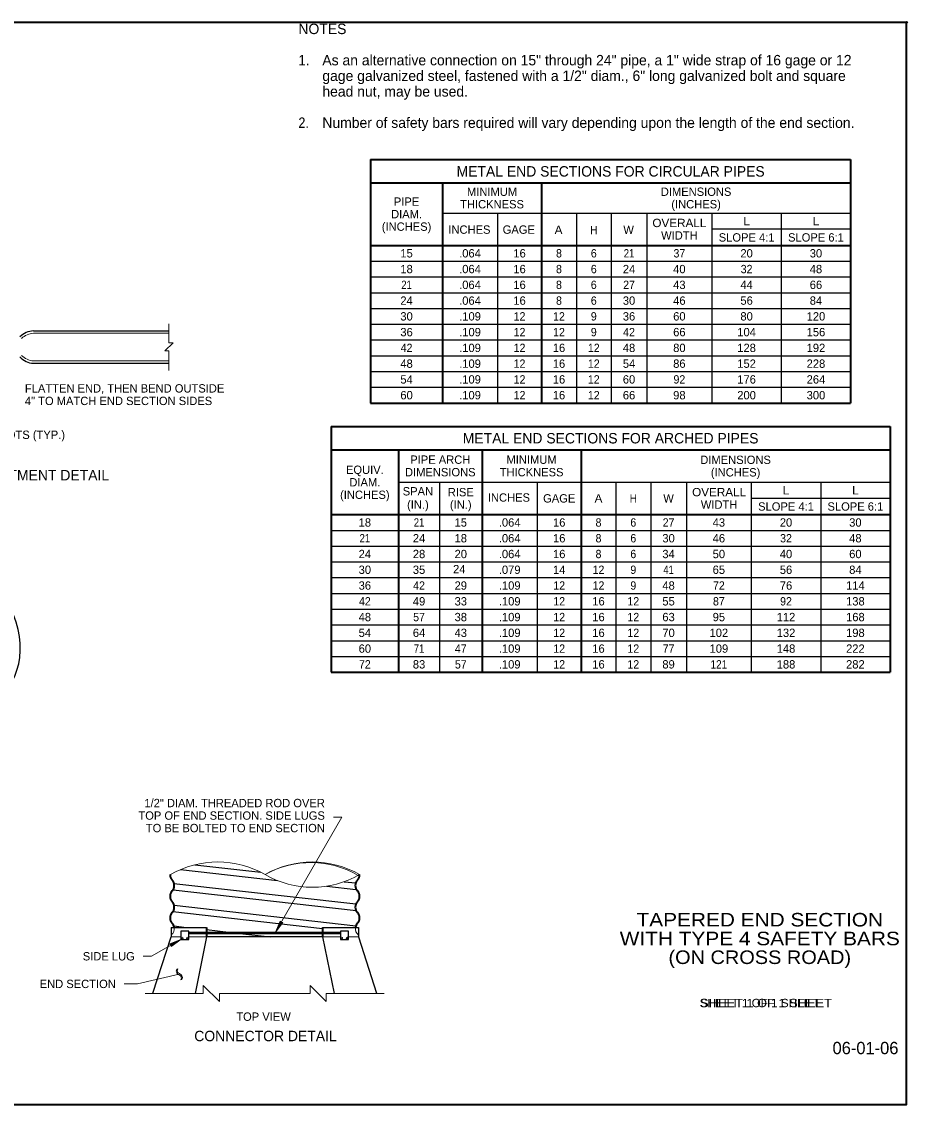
# Model space of a CAD drawing. Extents: x 99860 to 103153, y 99998 to 102077.
# Drawn here: x 101453 to 103153, y 100000 to 102077 of the extents above; entities that cross this region are included whole.
import ezdxf
from ezdxf.enums import TextEntityAlignment as Align

# ---------------------------------------------------------------- set-up
doc = ezdxf.new("R2010")
doc.units = 0
doc.header["$LTSCALE"] = 6.4
doc.header["$PDMODE"] = 32
doc.header["$PDSIZE"] = 3.2
for name, color, linetype, lineweight in [('1', 7, 'Continuous', 35), ('15', 7, 'Continuous', 13), ('18', 7, 'Continuous', 25), ('19', 7, 'Continuous', 25), ('20', 7, 'Continuous', 13), ('6', 7, 'Continuous', 25)]:
    doc.layers.add(name, color=color, linetype=linetype, lineweight=lineweight)
for name, color, linetype in [('11', 7, 'Continuous'), ('60', 7, 'Continuous'), ('62', 7, 'Continuous'), ('63', 7, 'Continuous')]:
    doc.layers.add(name, color=color, linetype=linetype)

msp = doc.modelspace()

# ---------------------------------------------------------------- hatches: boundary and pattern name
at = {"layer": '15'}
for points in [[(101939.857, 100330.015), (101948.687, 100351.278), (101950.744, 100348.871), (101953.857, 100348.293)], [(101758.02, 100316.136), (101736.757, 100307.306), (101739.164, 100305.249), (101739.742, 100302.136)]]:
    msp.add_hatch(color=256, dxfattribs=at).paths.add_polyline_path(points)

# ---------------------------------------------------------------- linework, layer by layer
at = {"layer": '1'}
msp.add_lwpolyline([(99862, 99999.5), (103151, 99999.5), (103151, 102075.5), (99862, 102075.5)], close=True, dxfattribs=at)
at = {"layer": '15'}
for p, q in [((101939.857, 100330.015), (102067.375, 100550.882)), ((102051.375, 100550.882), (102067.375, 100550.882)), ((101758.02, 100316.135), (101701.728, 100283.635)), ((101685.728, 100283.635), (101701.728, 100283.635))]:
    msp.add_line(p, q, dxfattribs=at)
for points in [[(101735.376, 101497.024), (101735.376, 101460.814), (101743.119, 101460.814), (101727.633, 101445.328), (101735.376, 101445.328), (101735.376, 101407.991)], [(101919.135, 100212.225), (101832.027, 100212.225), (101832.027, 100196.739), (101801.055, 100227.711), (101801.055, 100212.225), (101689.467, 100212.225)], [(102148.494, 100212.225), (102037.215, 100212.225), (102037.215, 100196.739), (102006.243, 100227.711), (102006.243, 100212.225), (101919.135, 100212.225)]]:
    msp.add_lwpolyline(points, dxfattribs=at)
for points in [[(101939.857, 100330.015), (101948.687, 100351.278), (101950.744, 100348.871), (101953.857, 100348.293)], [(101758.02, 100316.136), (101736.757, 100307.306), (101739.164, 100305.249), (101739.742, 100302.136)]]:
    msp.add_lwpolyline(points, close=True, dxfattribs=at)
at = {"layer": '18'}
for p, q in [((101475.087, 101483.84), (101734.737, 101483.84)), ((101475.147, 101421.75), (101734.737, 101421.75)), ((101739.76, 100339.165), (101807.66, 100339.165)), ((101739.76, 100339.165), (101739.76, 100320.995)), ((101773.44, 100330.015), (102064.31, 100330.015)), ((101773.44, 100327.585), (102064.31, 100327.585)), ((101704.23, 100212.705), (101739.772, 100320.991)), ((101807.66, 100320.995), (101785.77, 100212.495)), ((102030.31, 100320.995), (102052.2, 100212.495))]:
    msp.add_line(p, q, dxfattribs=at)
at = {"layer": '18', "lineweight": 13}
for p, q in [((101475.287, 101479.37), (101734.737, 101479.37)), ((101475.147, 101426.21), (101734.737, 101426.21))]:
    msp.add_line(p, q, dxfattribs=at)
at = {"layer": '18', "lineweight": 35}
for p, q in [((101807.66, 100339.165), (101807.66, 100330.015)), ((101807.66, 100327.585), (101807.66, 100320.995)), ((102030.31, 100339.165), (102030.31, 100330.015)), ((102030.31, 100327.585), (102030.31, 100320.995))]:
    msp.add_line(p, q, dxfattribs=at)
at = {"layer": '18'}
for points in [[(101773.44, 100331.635), (101758.02, 100331.635), (101758.02, 100316.135), (101773.44, 100316.135)], [(102079.81, 100331.635), (102064.31, 100331.635), (102064.31, 100316.135), (102079.81, 100316.135)]]:
    msp.add_lwpolyline(points, close=True, dxfattribs=at)
msp.add_lwpolyline([(102030.31, 100339.165), (102099.42, 100339.165), (102099.42, 100320.995), (102133.67, 100212.915)], dxfattribs=at)
for centre, radius, start, end in [((101479.006, 101439.497), 44.512, 94.97013, 131.98006), ((101476.264, 101458.194), 36.47, 222.16871, 268.2497)]:
    msp.add_arc(centre, radius, start, end, dxfattribs=at)
at = {"layer": '18', "lineweight": 13}
for centre, radius, start, end in [((101479.006, 101439.497), 40.045, 94.97013, 131.98006), ((101476.264, 101458.194), 32.003, 222.16871, 268.2497), ((101760.662, 100318.575), 1.613, 0, 180), ((101760.662, 100318.575), 1.613, 180, 0), ((101770.738, 100318.575), 1.613, 0, 180), ((101770.738, 100318.575), 1.613, 180, 0), ((102066.998, 100318.575), 1.613, 0, 180), ((102066.998, 100318.575), 1.613, 180, 0), ((102077.074, 100318.575), 1.613, 0, 180), ((102077.074, 100318.575), 1.613, 180, 0)]:
    msp.add_arc(centre, radius, start, end, dxfattribs=at)
at = {"layer": '19', "lineweight": 35}
for p, q in [((102122.379, 101812.42), (103043.649, 101812.42)), ((102122.379, 101812.42), (102122.379, 101345.22)), ((103043.649, 101812.42), (103043.649, 101345.22)), ((102122.379, 101767.79), (103043.649, 101767.79)), ((102260.359, 101767.79), (102260.359, 101345.22)), ((102450.519, 101767.79), (102450.519, 101345.22)), ((102122.379, 101647.72), (103043.649, 101647.72)), ((102122.379, 101345.22), (103043.649, 101345.22)), ((102046.594, 101300.22), (102046.594, 100828.7)), ((102046.594, 101300.22), (103119.434, 101300.22)), ((103119.434, 101300.22), (103119.434, 100828.7)), ((102046.594, 101255.22), (103119.434, 101255.22)), ((102175.994, 101255.22), (102175.994, 100828.7)), ((102336.224, 101255.22), (102336.224, 100828.7)), ((102526.384, 101255.22), (102526.384, 100828.7)), ((102046.594, 101131.2), (103119.434, 101131.2)), ((102046.594, 100828.7), (103119.434, 100828.7))]:
    msp.add_line(p, q, dxfattribs=at)
at = {"layer": '19'}
for p, q in [((102260.359, 101709.74), (103043.649, 101709.74)), ((102365.949, 101709.74), (102365.949, 101345.22)), ((102517.289, 101709.74), (102517.289, 101345.22)), ((102584.129, 101709.74), (102584.129, 101345.22)), ((102652.639, 101709.74), (102652.639, 101345.22)), ((102777.379, 101709.74), (102777.379, 101345.22)), ((102910.689, 101709.74), (102910.689, 101345.22)), ((103043.849, 101678.63), (102777.529, 101678.63)), ((102122.379, 101617.47), (103043.649, 101617.47)), ((102122.379, 101587.22), (103043.649, 101587.22)), ((102122.379, 101556.97), (103043.649, 101556.97)), ((102122.379, 101526.72), (103043.649, 101526.72)), ((102122.379, 101496.47), (103043.649, 101496.47)), ((102122.379, 101466.22), (103043.649, 101466.22)), ((102122.379, 101435.97), (103043.649, 101435.97)), ((102122.379, 101405.72), (103043.649, 101405.72)), ((102122.379, 101375.47), (103043.649, 101375.47)), ((102175.994, 101193.42), (103119.434, 101193.42)), ((102254.634, 101193.42), (102254.634, 100828.7)), ((102442.364, 101193.42), (102442.364, 100828.7)), ((102593.154, 101193.42), (102593.154, 100828.7)), ((102659.994, 101193.42), (102659.994, 100828.7)), ((102728.504, 101193.42), (102728.504, 100828.7)), ((102853.114, 101193.42), (102853.114, 100828.7)), ((102986.274, 101193.42), (102986.274, 100828.7)), ((103119.434, 101162.31), (102853.114, 101162.31)), ((102046.594, 101100.95), (103119.434, 101100.95)), ((102046.594, 101070.7), (103119.434, 101070.7)), ((102046.594, 101040.45), (103119.434, 101040.45)), ((102046.594, 101010.2), (103119.434, 101010.2)), ((102046.594, 100979.95), (103119.434, 100979.95)), ((102046.594, 100949.7), (103119.434, 100949.7)), ((102046.594, 100919.45), (103119.434, 100919.45)), ((102046.594, 100889.2), (103119.434, 100889.2)), ((102046.594, 100858.95), (103119.434, 100858.95))]:
    msp.add_line(p, q, dxfattribs=at)
at = {"layer": '20'}
for p, q in [((101755.18, 100249.005), (101674.84, 100230.605)), ((101752.248, 100259.85), (101750.418, 100258.793)), ((101649.34, 100230.605), (101674.84, 100230.605)), ((101758.15, 100238.156), (101759.981, 100239.214))]:
    msp.add_line(p, q, dxfattribs=at)
for points in [[(101750.417, 100258.792), (101749.652, 100256.957), (101749.362, 100255.189), (101749.557, 100253.494), (101750.233, 100251.867), (101751.983, 100249.784), (101755.604, 100247.263), (101757.594, 100245.879), (101758.544, 100244.717), (101759.023, 100243.378)], [(101759.98, 100239.213), (101760.725, 100241.226), (101760.997, 100242.984), (101760.819, 100244.591), (101760.172, 100246.122), (101758.629, 100248.045), (101755.226, 100250.315), (101753.138, 100251.782), (101751.884, 100253.235), (101751.386, 100254.472), (101751.238, 100255.825), (101751.51, 100257.539), (101752.247, 100259.849)], [(101759.023, 100243.378), (101759.079, 100241.733), (101758.149, 100238.156)]]:
    msp.add_lwpolyline(points, dxfattribs=at)
at = {"layer": '6'}
for p, q in [((101784.807, 100459.176), (101911.414, 100444.876)), ((101757.389, 100449.9), (101943.398, 100428.893)), ((101743.141, 100411.368), (102094.317, 100371.708)), ((101744.941, 100423.537), (102094.307, 100384.078)), ((102038.236, 100418.183), (102093.784, 100411.909)), ((102071.867, 100426.753), (102093.773, 100424.279)), ((101743.023, 100369.613), (102030.31, 100337.169)), ((101744.996, 100381.763), (102094.147, 100342.328)), ((101744.428, 100341.918), (101768.802, 100339.165)), ((101807.66, 100334.776), (101849.814, 100330.015)), ((101871.329, 100327.585), (101929.675, 100320.995)), ((102030.38, 100320.995), (101807.66, 100320.995))]:
    msp.add_line(p, q, dxfattribs=at)
at = {"layer": '6', "lineweight": 13}
for p, q in [((101739.76, 100320.995), (101758.02, 100320.995)), ((101773.44, 100320.995), (101807.66, 100320.995)), ((102030.31, 100320.995), (102064.31, 100320.995)), ((102099.42, 100320.995), (102079.81, 100320.995))]:
    msp.add_line(p, q, dxfattribs=at)
for centre, radius, start, end in [((101829.047, 100283.241), 181.411, 60, 120), ((102010.458, 100283.241), 181.411, 60, 120), ((102007.856, 100282.958), 180.371, 59.81272, 119.23918), ((102010.458, 100597.455), 181.411, 240, 300), ((101730.359, 100336.334), 15.137, 308.39192, 10.76797), ((102108.128, 100336.526), 15.137, 169.95753, 234.88169)]:
    msp.add_arc(centre, radius, start, end, dxfattribs=at)
at = {"layer": '6', "lineweight": 35}
for centre, start, end in [((101752.46, 100440.358), 180.0381, 223.11161), ((102086.027, 100440.358), 316.88838, 359.96189), ((101730.359, 100419.477), 316.88838, 43.11162), ((102108.128, 100419.477), 136.88838, 223.11161), ((101752.46, 100398.787), 136.88838, 223.11162), ((102086.027, 100398.787), 316.88838, 43.11162), ((101730.359, 100377.905), 316.88838, 43.11162), ((102108.128, 100377.905), 136.88838, 223.11161), ((101752.46, 100357.215), 136.88838, 223.11162), ((102086.027, 100357.215), 316.88838, 43.11162), ((101730.359, 100336.334), 10.76796, 43.11162), ((102108.128, 100336.526), 136.88838, 169.95753)]:
    msp.add_arc(centre, 15.137, start, end, dxfattribs=at)
at = {"layer": '6'}
msp.add_ellipse((101299.095, 100908.881), major_axis=(-114.131, 123.992), ratio=0.796016, start_param=2.84759693, end_param=5.70624229, dxfattribs=at)
at = {"layer": '60'}
msp.add_point((103151, 102075.5), dxfattribs=at)

# ---------------------------------------------------------------- texts
at = {"layer": '11'}
msp.add_text('06-01-06', height=23.62, dxfattribs=at).set_placement((103072.262, 100095.777), align=Align.CENTER)
at = {"layer": '19'}
for s, height, p in [('METAL END SECTIONS FOR CIRCULAR PIPES', 20, (102583.015, 101779.8)), ('MINIMUM', 16, (102355.44, 101742.765)), ('DIMENSIONS', 16, (102747.085, 101742.765)), ('PIPE', 16, (102191.37, 101723.755)), ('THICKNESS', 16, (102355.44, 101718.765)), ('(INCHES)', 16, (102747.085, 101718.765)), ('DIAM.', 16, (102191.37, 101699.755)), ('(INCHES)', 16, (102191.37, 101675.755)), ('INCHES', 16, (102312, 101670.06)), ('GAGE', 16, (102406.795, 101670.06)), ('W', 16, (102617.604, 101669.51)), ('WIDTH', 16, (102715.01, 101658.86)), ('SLOPE 4:1', 16, (102844.112, 101655.075)), ('SLOPE 6:1', 16, (102977.171, 101655.075)), ('15', 16, (102191.37, 101624.595)), ('.064', 16, (102313.155, 101624.595)), ('16', 16, (102408.235, 101624.595)), ('20', 16, (102844.035, 101624.595)), ('30', 16, (102977.17, 101624.595)), ('18', 16, (102191.37, 101594.345)), ('.064', 16, (102313.154, 101594.345)), ('16', 16, (102408.235, 101594.345)), ('24', 16, (102618.384, 101594.345)), ('40', 16, (102715.009, 101594.345)), ('48', 16, (102977.17, 101594.345)), ('.064', 16, (102313.154, 101564.095)), ('16', 16, (102408.235, 101564.095)), ('43', 16, (102715.009, 101564.095)), ('44', 16, (102844.035, 101564.095)), ('66', 16, (102977.17, 101564.095)), ('24', 16, (102191.37, 101533.845)), ('.064', 16, (102313.154, 101533.845)), ('16', 16, (102408.235, 101533.845)), ('30', 16, (102618.385, 101533.845)), ('46', 16, (102715.01, 101533.845)), ('56', 16, (102844.035, 101533.845)), ('84', 16, (102977.17, 101533.845)), ('30', 16, (102191.37, 101503.595)), ('.109', 16, (102313.154, 101503.595)), ('36', 16, (102618.384, 101503.595)), ('60', 16, (102715.009, 101503.595)), ('80', 16, (102844.035, 101503.595)), ('120', 16, (102977.17, 101503.595)), ('36', 16, (102191.37, 101473.345)), ('.109', 16, (102313.154, 101473.345)), ('66', 16, (102715.009, 101473.345)), ('104', 16, (102844.035, 101473.345)), ('156', 16, (102977.17, 101473.345)), ('.109', 16, (102313.154, 101443.095)), ('16', 16, (102483.904, 101443.095)), ('48', 16, (102618.384, 101443.095)), ('80', 16, (102715.009, 101443.095)), ('128', 16, (102844.035, 101443.095)), ('192', 16, (102977.17, 101443.095)), ('48', 16, (102191.37, 101412.845)), ('.109', 16, (102313.155, 101412.845)), ('16', 16, (102483.905, 101412.845)), ('54', 16, (102618.384, 101412.845)), ('86', 16, (102715.01, 101412.845)), ('152', 16, (102844.035, 101412.845)), ('228', 16, (102977.17, 101412.845)), ('54', 16, (102191.37, 101382.595)), ('.109', 16, (102313.154, 101382.595)), ('16', 16, (102483.904, 101382.595)), ('60', 16, (102618.384, 101382.595)), ('176', 16, (102844.035, 101382.595)), ('264', 16, (102977.17, 101382.595)), ('60', 16, (102191.37, 101352.345)), ('.109', 16, (102313.156, 101352.345)), ('16', 16, (102483.904, 101352.345)), ('66', 16, (102618.384, 101352.345)), ('98', 16, (102715.01, 101352.345)), ('200', 16, (102844.035, 101352.345)), ('300', 16, (102977.17, 101352.345)), ('METAL END SECTIONS FOR ARCHED PIPES', 20, (102583.018, 101267.72)), ('PIPE ARCH', 16, (102256.111, 101228.6)), ('MINIMUM', 16, (102431.306, 101228.6)), ('DIMENSIONS', 16, (102822.91, 101228.32)), ('EQUIV.', 16, (102111.296, 101209.21)), ('DIMENSIONS', 16, (102256.11, 101204.6)), ('THICKNESS', 16, (102431.306, 101204.6)), ('(INCHES)', 16, (102822.91, 101204.32)), ('DIAM.', 16, (102111.296, 101185.21)), ('SPAN', 16, (102213.123, 101167.92)), ('RISE', 16, (102295.431, 101166.31)), ('(INCHES)', 16, (102111.296, 101161.21)), ('(IN.)', 16, (102213.124, 101142.31)), ('(IN.)', 16, (102295.431, 101142.31)), ('INCHES', 16, (102387.866, 101155.96)), ('GAGE', 16, (102484.376, 101154.31)), ('W', 16, (102694.251, 101154.31)), ('WIDTH', 16, (102791.268, 101142.318)), ('SLOPE 4:1', 16, (102919.697, 101138.755)), ('SLOPE 6:1', 16, (103052.856, 101138.755)), ('18', 16, (102111.296, 101108.075)), ('15', 16, (102295.431, 101108.075)), ('.064', 16, (102389.296, 101108.075)), ('16', 16, (102484.376, 101108.075)), ('43', 16, (102790.811, 101108.075)), ('20', 16, (102919.697, 101108.075)), ('30', 16, (103052.857, 101108.075)), ('24', 16, (102215.316, 101077.825)), ('18', 16, (102295.431, 101077.825)), ('.064', 16, (102389.296, 101077.825)), ('16', 16, (102484.376, 101077.825)), ('30', 16, (102694.251, 101077.825)), ('46', 16, (102790.811, 101077.825)), ('48', 16, (103052.857, 101077.825)), ('24', 16, (102111.296, 101047.575)), ('28', 16, (102215.316, 101047.575)), ('20', 16, (102295.431, 101047.575)), ('.064', 16, (102389.296, 101047.575)), ('16', 16, (102484.376, 101047.575)), ('34', 16, (102694.251, 101047.575)), ('50', 16, (102790.811, 101047.575)), ('40', 16, (102919.697, 101047.575)), ('60', 16, (103052.857, 101047.575)), ('24', 16, (102292.556, 101018.528)), ('30', 16, (102111.296, 101017.325)), ('35', 16, (102215.316, 101017.325)), ('.079', 16, (102389.296, 101017.325)), ('14', 16, (102484.376, 101017.325)), ('65', 16, (102790.81, 101017.325)), ('56', 16, (102919.697, 101017.325)), ('84', 16, (103052.856, 101017.325)), ('36', 16, (102111.296, 100987.075)), ('29', 16, (102295.431, 100987.075)), ('.109', 16, (102389.296, 100987.075)), ('48', 16, (102694.251, 100987.075)), ('76', 16, (102919.697, 100987.075)), ('114', 16, (103052.857, 100987.075)), ('49', 16, (102215.316, 100956.825)), ('33', 16, (102295.431, 100956.825)), ('.109', 16, (102389.296, 100956.825)), ('16', 16, (102559.771, 100956.825)), ('55', 16, (102694.251, 100956.825)), ('138', 16, (103052.857, 100956.825)), ('48', 16, (102111.296, 100926.575)), ('38', 16, (102295.431, 100926.575)), ('.109', 16, (102389.296, 100926.575)), ('16', 16, (102559.771, 100926.575)), ('63', 16, (102694.251, 100926.575)), ('95', 16, (102790.811, 100926.575)), ('112', 16, (102919.697, 100926.575)), ('168', 16, (103052.857, 100926.575)), ('54', 16, (102111.296, 100896.325)), ('64', 16, (102215.316, 100896.325)), ('43', 16, (102295.431, 100896.325)), ('.109', 16, (102389.296, 100896.325)), ('16', 16, (102559.771, 100896.325)), ('70', 16, (102694.251, 100896.325)), ('102', 16, (102790.81, 100896.325)), ('132', 16, (102919.697, 100896.325)), ('198', 16, (103052.856, 100896.325)), ('60', 16, (102111.296, 100866.075)), ('.109', 16, (102389.296, 100866.075)), ('16', 16, (102559.771, 100866.075)), ('109', 16, (102790.81, 100866.075)), ('148', 16, (102919.697, 100866.075)), ('222', 16, (103052.856, 100866.075)), ('83', 16, (102215.316, 100835.825)), ('.109', 16, (102389.296, 100835.825)), ('16', 16, (102559.771, 100835.825)), ('89', 16, (102694.251, 100835.825)), ('188', 16, (102919.697, 100835.825)), ('282', 16, (103052.856, 100835.825))]:
    msp.add_text(s, height=height, dxfattribs=at).set_placement(p, align=Align.CENTER)
for s, width, p in [('OVERALL', 1.05, (102715.011, 101682.86)), ('L', 1.05, (102844.112, 101686.185)), ('L', 1.05, (102977.272, 101686.185)), ('A', 1.05, (102483.116, 101669.7)), ('H', 0.9, (102550.85, 101669.27)), ('8', 0.95, (102483.905, 101624.595)), ('6', 0.95, (102550.71, 101624.595)), ('21', 0.85, (102618.386, 101624.595)), ('37', 0.95, (102715.01, 101624.595)), ('8', 0.95, (102483.905, 101594.345)), ('6', 0.95, (102550.71, 101594.345)), ('32', 0.95, (102844.035, 101594.345)), ('21', 0.85, (102191.37, 101564.095)), ('8', 0.95, (102483.905, 101564.095)), ('6', 0.95, (102550.71, 101564.095)), ('27', 0.95, (102618.384, 101564.095)), ('8', 0.95, (102483.905, 101533.845)), ('6', 0.95, (102550.711, 101533.845)), ('12', 0.95, (102408.235, 101503.595)), ('12', 0.95, (102483.904, 101503.595)), ('9', 0.95, (102550.71, 101503.595)), ('12', 0.95, (102408.235, 101473.345)), ('12', 0.95, (102483.904, 101473.345)), ('9', 0.95, (102550.711, 101473.345)), ('42', 0.95, (102618.385, 101473.345)), ('42', 0.95, (102191.37, 101443.095)), ('12', 0.95, (102408.235, 101443.095)), ('12', 0.95, (102550.71, 101443.095)), ('12', 0.95, (102408.235, 101412.845)), ('12', 0.95, (102550.71, 101412.845)), ('12', 0.95, (102408.235, 101382.595)), ('12', 0.95, (102550.71, 101382.595)), ('92', 0.95, (102715.009, 101382.595)), ('12', 0.95, (102408.235, 101352.345)), ('12', 0.95, (102550.71, 101352.345)), ('OVERALL', 1.05, (102791.269, 101166.318)), ('L', 1.05, (102919.697, 101169.865)), ('L', 1.05, (103052.856, 101169.865)), ('A', 1.05, (102559.771, 101154.31)), ('H', 0.9, (102626.576, 101154.31)), ('21', 0.85, (102215.317, 101108.075)), ('8', 0.95, (102559.772, 101108.075)), ('6', 0.95, (102626.576, 101108.075)), ('27', 0.95, (102694.251, 101108.075)), ('21', 0.85, (102111.297, 101077.825)), ('8', 0.95, (102559.772, 101077.825)), ('6', 0.95, (102626.576, 101077.825)), ('32', 0.95, (102919.697, 101077.825)), ('8', 0.95, (102559.772, 101047.575)), ('6', 0.95, (102626.576, 101047.575)), ('12', 0.95, (102559.771, 101017.325)), ('9', 0.95, (102626.576, 101017.325)), ('41', 0.85, (102694.252, 101017.325)), ('42', 0.95, (102215.316, 100987.075)), ('12', 0.95, (102484.376, 100987.075)), ('12', 0.95, (102559.771, 100987.075)), ('9', 0.95, (102626.576, 100987.075)), ('72', 0.95, (102790.811, 100987.075)), ('42', 0.95, (102111.296, 100956.825)), ('12', 0.95, (102484.376, 100956.825)), ('12', 0.95, (102626.576, 100956.825)), ('87', 0.95, (102790.811, 100956.825)), ('92', 0.95, (102919.697, 100956.825)), ('57', 0.95, (102215.316, 100926.575)), ('12', 0.95, (102484.376, 100926.575)), ('12', 0.95, (102626.576, 100926.575)), ('12', 0.95, (102484.376, 100896.325)), ('12', 0.95, (102626.576, 100896.325)), ('71', 0.85, (102215.316, 100866.075)), ('47', 0.95, (102295.431, 100866.075)), ('12', 0.95, (102484.376, 100866.075)), ('12', 0.95, (102626.576, 100866.075)), ('77', 0.95, (102694.251, 100866.075)), ('72', 0.95, (102111.296, 100835.825)), ('57', 0.95, (102295.431, 100835.825)), ('12', 0.95, (102484.376, 100835.825)), ('12', 0.95, (102626.576, 100835.825)), ('121', 0.9, (102790.812, 100835.825))]:
    msp.add_text(s, height=16, dxfattribs=dict(at, width=width)).set_placement(p, align=Align.CENTER)
at = {"layer": '20'}
for s, height, p in [('NOTES', 20, (101983.76, 102053.227)), ('As an alternative connection on 15" through 24" pipe, a 1" wide strap of 16 gage or 12', 20, (102029.712, 101993.227)), ('gage galvanized steel, fastened with a 1/2" diam., 6" long galvanized bolt and square', 20, (102029.712, 101963.227)), ('head nut, may be used.', 20, (102029.712, 101933.227)), ('Number of safety bars required will vary depending upon the length of the end section.', 20, (102029.712, 101873.227)), ('FLATTEN END, THEN BEND OUTSIDE', 16, (101458.79, 101365.37)), ('4" TO MATCH END SECTION SIDES', 16, (101458.79, 101341.37)), ('9/16" x 1" SLOTS (TYP.)', 16, (101300.63, 101276.352))]:
    msp.add_text(s, height=height, dxfattribs=at).set_placement(p)
for s, width, p in [('1.', 0.95, (101983.76, 101993.227)), ('2.', 0.9, (101983.76, 101873.227))]:
    msp.add_text(s, height=20, dxfattribs=dict(at, width=width)).set_placement(p)
for s, height, p in [('SAFETY BAR END TREATMENT DETAIL', 20, (101369.321, 101196.835)), ('TOP VIEW', 16, (101916.832, 100159.757)), ('CONNECTOR DETAIL', 20, (101920.603, 100120.647))]:
    msp.add_text(s, height=height, dxfattribs=at).set_placement(p, align=Align.CENTER)
for s, p in [('1/2" DIAM. THREADED ROD OVER', (102034.519, 100569.655)), ('TOP OF END SECTION. SIDE LUGS', (102034.519, 100545.655)), ('TO BE BOLTED TO END SECTION', (102034.519, 100521.655)), ('SIDE LUG', (101669.73, 100275.635)), ('END SECTION', (101633.342, 100222.605))]:
    msp.add_text(s, height=16, dxfattribs=at).set_placement(p, align=Align.RIGHT)
at = {"layer": '62'}
for width, p in [(1.05, (102869.354, 100185.938)), (1.15, (102881.29, 100185.938))]:
    msp.add_text('SHEET 1 OF 1 SHEET', height=16, dxfattribs=dict(at, width=width)).set_placement(p, align=Align.CENTER)
at = {"layer": '63'}
for s, width, p in [('TAPERED END SECTION', 1.15, (102869.348, 100340.799)), ('WITH TYPE 4 SAFETY BARS', 1.15, (102869.348, 100304.799)), ('(ON CROSS ROAD)', 1.1, (102869.347, 100268.799))]:
    msp.add_text(s, height=26, dxfattribs=dict(at, width=width)).set_placement(p, align=Align.CENTER)

doc.saveas('drawing.dxf')
